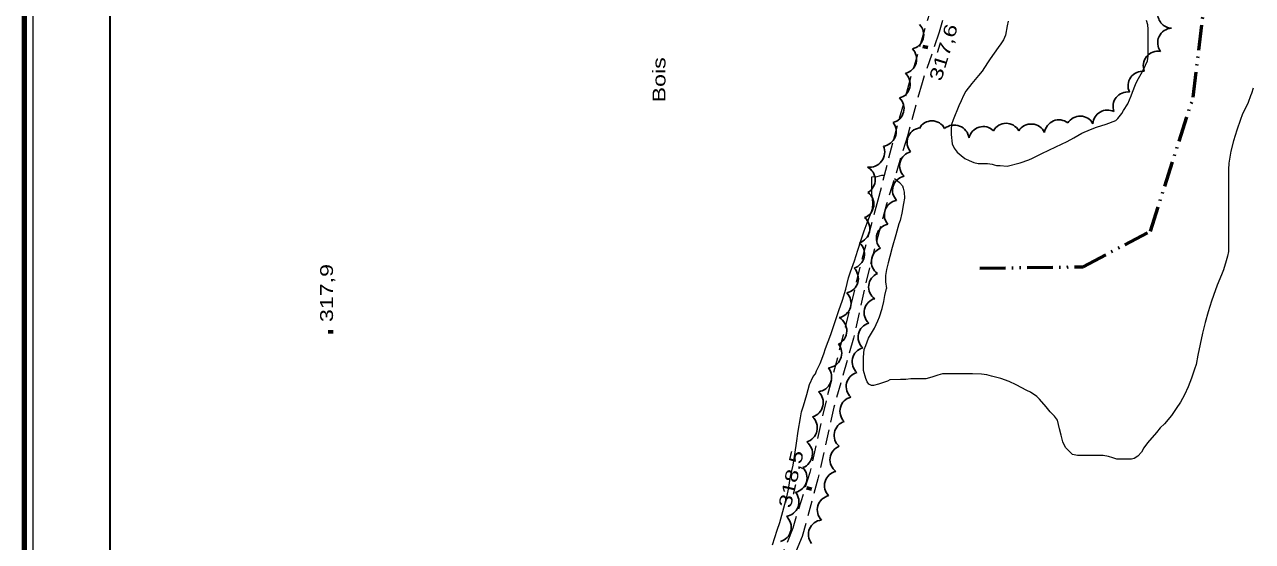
# Model space of a CAD drawing. Extents: x 240591 to 242335, y 5323482 to 5326937.
# Drawn here: x 240590.8 to 240877.4, y 5323830.7 to 5323951.4 of the extents above; entities that cross this region are included whole.
import ezdxf
from ezdxf.enums import TextEntityAlignment as Align

# ---------------------------------------------------------------- set-up
doc = ezdxf.new("R2010")
doc.units = 0
doc.header["$LTSCALE"] = 1.2
for name, pattern in [('DASH_DOUBLE_DOT', [9.2, 5, -1.2, 0.3, -1.2, 0.3, -1.2]), ('LONG_DASHED', [7.5, 6, -1.5]), ('MEDIUM_DASHED', [4.5, 3, -1.5])]:
    doc.linetypes.add(name, pattern=pattern)
for name, color, linetype, lineweight in [('19', 7, 'Continuous', 13), ('2', 7, 'Continuous', 13), ('3', 7, 'Continuous', 140), ('4', 7, 'DASH_DOUBLE_DOT', 53), ('44', 7, 'Continuous', 25), ('60', 7, 'Continuous', 35)]:
    doc.layers.add(name, color=color, linetype=linetype, lineweight=lineweight)

msp = doc.modelspace()

# ---------------------------------------------------------------- linework, layer by layer
at = {"layer": '19', "linetype": 'MEDIUM_DASHED'}
for points in [[(240808, 5323962.7), (240804.3, 5323949.6), (240800.3, 5323937.8), (240796.9, 5323925.3), (240792, 5323909.4), (240788, 5323894.6), (240784.3, 5323878.1), (240779.7, 5323862), (240776, 5323845.3), (240772.3, 5323831.8), (240767.8, 5323821.1)], [(240804.2, 5323960.8), (240800.7, 5323949.6), (240797.4, 5323938.1), (240793.4, 5323923.7), (240790, 5323910.4), (240785.8, 5323894.7), (240781.9, 5323878.8), (240777.9, 5323863.5), (240774.1, 5323846.8), (240770.1, 5323833.8), (240765.6, 5323822.3)]]:
    msp.add_lwpolyline(points, dxfattribs=at)
at = {"layer": '2'}
for points in [[(240820.4, 5323952.2), (240820.2, 5323951.1), (240819.8, 5323948.9), (240819.3, 5323947.8), (240818.7, 5323946.9), (240818.1, 5323946), (240816.2, 5323943.4), (240815.6, 5323942.4), (240814.3, 5323940.5), (240813.5, 5323939.5), (240811.9, 5323937.6), (240810.5, 5323935.8), (240810, 5323934.8), (240809.4, 5323933.6), (240808.9, 5323932.4), (240807.6, 5323929.1), (240807.2, 5323928), (240807.1, 5323926.9), (240807.1, 5323925.7), (240807.3, 5323923.5), (240807.8, 5323922.5), (240808.5, 5323921.6), (240809.4, 5323920.8), (240810.3, 5323920.1), (240811.3, 5323919.6), (240812.4, 5323919.2), (240813.4, 5323918.9), (240814.3, 5323918.9), (240815.6, 5323918.9), (240816.7, 5323918.8), (240817.1, 5323918.6), (240817.7, 5323918.5), (240818.5, 5323918.5), (240820.2, 5323918.3)], [(240820.2, 5323918.3), (240823.2, 5323919.1), (240825.2, 5323919.8), (240826.1, 5323920.2), (240828.3, 5323921.3), (240831.5, 5323922.8), (240834.2, 5323924.1), (240835.7, 5323924.9), (240837.6, 5323926), (240839.6, 5323926.9), (240841, 5323927.4), (240843.3, 5323928.1), (240845.5, 5323929), (240846, 5323929.4), (240846.9, 5323930.6), (240847.3, 5323931.3), (240848.3, 5323932.9), (240849.1, 5323934.7), (240849.4, 5323935.6), (240850.1, 5323937.4), (240850.5, 5323938.2), (240851.8, 5323940.4), (240852.5, 5323941.9), (240852.9, 5323942.9), (240853.1, 5323944), (240853.1, 5323945), (240853.1, 5323947.1), (240853.1, 5323950.3), (240853, 5323951.3), (240852.7, 5323952.3)], [(240788.6, 5323915.8), (240789.8, 5323915.9), (240790.9, 5323916.2), (240791.5, 5323916.2)], [(240793.9, 5323915.4), (240794.2, 5323915.2), (240795, 5323914.5), (240795.7, 5323913.7), (240795.9, 5323913.2), (240796.1, 5323912.2), (240796.2, 5323910.8), (240796, 5323909.6), (240795.6, 5323907.3), (240795.2, 5323905.6), (240794.9, 5323904.8), (240794.2, 5323902.3), (240793.3, 5323899.3), (240792.8, 5323897.2), (240792.4, 5323895.7), (240792, 5323894.2), (240791.8, 5323892.8), (240791.8, 5323891.3), (240792, 5323889.7)]]:
    msp.add_lwpolyline(points, dxfattribs=at)
at = {"layer": '2', "linetype": 'LONG_DASHED'}
for points in [[(240877.6, 5323936.5), (240877.2, 5323935.3), (240877, 5323934.7), (240876.4, 5323933.2), (240875, 5323930.3), (240874.6, 5323929.2), (240873.8, 5323926.7), (240873, 5323924.2), (240872.4, 5323921.8), (240871.9, 5323919), (240871.8, 5323917.5), (240871.8, 5323916), (240871.8, 5323913.2), (240871.8, 5323910.5), (240871.8, 5323907.9), (240871.8, 5323905.3), (240871.8, 5323901.8), (240871.8, 5323898.4), (240871.6, 5323897.3), (240871.3, 5323896.2), (240870.7, 5323894.1), (240870.2, 5323892.9), (240869.2, 5323890.5), (240868.3, 5323888.1), (240867.9, 5323886.8), (240867.1, 5323884.3), (240866.4, 5323881.8), (240865.8, 5323879.3), (240865.2, 5323876.7), (240864.7, 5323874.2), (240864.3, 5323872), (240863.9, 5323870.9), (240863.2, 5323868.8), (240862.4, 5323866.8), (240861.6, 5323864.9), (240860.6, 5323863.2), (240859.6, 5323861.7), (240858.5, 5323860.1), (240856.9, 5323858.1), (240855.9, 5323857.2), (240855, 5323856.1), (240852.9, 5323853.7), (240852.1, 5323852.5), (240851.5, 5323851.5), (240850.7, 5323850.6), (240849.8, 5323850), (240849.2, 5323849.9), (240848.6, 5323849.9), (240845.8, 5323849.9), (240844.8, 5323850.2), (240843.8, 5323850.5), (240842.6, 5323850.7)], [(240765.4, 5323829.9), (240766.5, 5323833.3), (240767.1, 5323835.1), (240768, 5323838.5), (240768.8, 5323841.4), (240769.1, 5323842.9), (240769.6, 5323845.8), (240770.2, 5323848.5), (240770.7, 5323851.5), (240771, 5323853.6), (240771.4, 5323856.4), (240771.9, 5323859.5), (240772.2, 5323860.9), (240772.6, 5323862.3), (240773.4, 5323865), (240774, 5323867.3), (240774.9, 5323869.2), (240775.4, 5323869.8), (240775.7, 5323870.5), (240776.5, 5323872.2), (240777.4, 5323874.5), (240777.8, 5323875.7), (240779, 5323879), (240780.1, 5323882.3), (240780.9, 5323884.6), (240781.7, 5323887), (240782.5, 5323889.6), (240783.1, 5323892.2), (240783.6, 5323893.6), (240784.5, 5323896.2), (240785.3, 5323898.7), (240786.1, 5323901.1), (240786.8, 5323903.2), (240787.5, 5323905.1), (240788.2, 5323906.9), (240788.7, 5323908.4), (240788.8, 5323909.6), (240788.7, 5323910.7), (240788.6, 5323911.9), (240788.6, 5323913.4), (240788.6, 5323915.8)], [(240842.6, 5323850.7), (240841.9, 5323850.7), (240839.2, 5323850.7), (240836.6, 5323850.7), (240835.4, 5323851), (240834.8, 5323851.6), (240833.9, 5323852.5), (240833.5, 5323853.2), (240833.2, 5323853.9), (240832.8, 5323855.5), (240832.4, 5323857), (240831.9, 5323859), (240831.2, 5323859.9), (240830.2, 5323860.9), (240829.3, 5323862.1), (240827.7, 5323863.9), (240827.1, 5323864.5), (240825.6, 5323865.5), (240824.8, 5323865.9), (240822.3, 5323867.2), (240820.6, 5323868), (240818.7, 5323868.7), (240816.5, 5323869.3), (240815.4, 5323869.6), (240814.2, 5323869.7), (240812.1, 5323869.8), (240810.3, 5323869.8), (240807.7, 5323869.8), (240805.1, 5323869.8), (240804, 5323869.5), (240802.6, 5323869), (240801.2, 5323868.6), (240800.6, 5323868.6), (240797.7, 5323868.6), (240796.5, 5323868.5), (240795.3, 5323868.5), (240792.8, 5323868.4), (240792.2, 5323868.1), (240790.1, 5323867.4), (240789, 5323867.1), (240788.5, 5323867.1), (240787.9, 5323867.4), (240787.5, 5323867.9), (240787.2, 5323868.7), (240786.6, 5323870.6), (240786.6, 5323871.6), (240786.6, 5323873.7), (240786.8, 5323875.5), (240787.2, 5323876.4), (240787.8, 5323878.1), (240788.7, 5323879.7), (240789.2, 5323880.5), (240790, 5323882.2), (240790.4, 5323883.1), (240791, 5323885.1), (240791.4, 5323886.7), (240791.6, 5323888.1), (240792, 5323889.7)]]:
    msp.add_lwpolyline(points, dxfattribs=at)
at = {"layer": '3'}
for p, q in [((240801, 5323945.8), (240801.2, 5323946.6)), ((240662.3, 5323879.2), (240662.3, 5323880)), ((240773.9, 5323842.6), (240774.1, 5323843.4))]:
    msp.add_line(p, q, dxfattribs=at)
at = {"layer": '4'}
msp.add_lwpolyline([(240813.8, 5323894.5), (240837.9, 5323894.8), (240853.6, 5323903.1), (240863.6, 5323934.4), (240867.4, 5323966.2), (240874.6, 5323997.3), (240880.9, 5324027.7), (240887.7, 5324063.3), (240891.8, 5324094.2), (240896.6, 5324123.1), (240898.9, 5324148.6), (240898.9, 5324169.8), (240897.6, 5324189.2), (240897.7, 5324201.4)], dxfattribs=at)
at = {"layer": '44'}
for centre, radius, start, end in [((240802.62, 5323925.541), 3.351, 27.92996, 151.68225), ((240807.813, 5323924.429), 3.489, 7.75394, 129.79364), ((240800.15, 5323923.9), 3.358, 98.34055, 221.61662), ((240798.46, 5323918.382), 3.389, 104.011, 225.61465), ((240791.212, 5323890.133), 3.38, 113.21534, 235.13197), ((240775.741, 5323869.075), 3.457, 276.45615, 38.14352), ((240773.797, 5323863.102), 3.448, 285.53051, 47.41147), ((240772.404, 5323857.217), 3.455, 286.24113, 47.89776), ((240771.27, 5323851.154), 3.457, 290.65989, 52.59729), ((240770.016, 5323845.518), 3.449, 282.46556, 44.15418), ((240768.142, 5323839.921), 3.439, 278.50349, 40.40673), ((240766.317, 5323833.982), 3.448, 285.53051, 47.41147)]:
    msp.add_arc(centre, radius, start, end, dxfattribs=at)
for centre, major_axis, ratio, start_param, end_param in [((240858.723, 5323953.882), (-2.989, -1.624), 0.982656, 5.6144268, 7.3004285), ((240797.306, 5323949.008), (3.255, -0.955), 0.999635, 5.2187518, 7.3432747), ((240858.7, 5323947.142), (-2.654, 2.122), 0.997268, 5.4414369, 7.597625), ((240795.648, 5323943.304), (2.949, -1.678), 0.999926, 5.4593403, 7.5848665), ((240855.383, 5323941.73), (-2.591, 2.277), 0.997201, 5.2577619, 7.3799209), ((240794.133, 5323937.494), (3.308, -0.769), 0.998722, 5.2168221, 7.3432066), ((240851.809, 5323937.066), (-2.805, 1.974), 0.997536, 5.2159353, 7.3369463), ((240792.7, 5323931.788), (3.292, -0.85), 0.998545, 5.2172951, 7.3390435), ((240848.28, 5323932.233), (-1.983, -2.767), 0.999937, 3.6368045, 5.6841444), ((240843.586, 5323928.003), (0.119, -3.407), 0.999846, 2.6520936, 4.6148704), ((240790.888, 5323926.386), (-0.474, 3.366), 0.999994, 3.1173898, 5.2435517), ((240819.92, 5323924.934), (-0.019, 3.386), 0.996974, 5.2142814, 7.3406298), ((240825.773, 5323924.697), (0.224, 3.454), 0.999951, 5.2202413, 7.3434146), ((240832.24, 5323925.759), (-1.29, 3.117), 0.997204, 5.2161728, 7.3373189), ((240837.214, 5323926.648), (0.314, 3.346), 0.999977, 5.2910443, 7.402616), ((240814.586, 5323924.16), (-0.951, 3.261), 0.999994, 5.2214567, 7.3505676), ((240788.059, 5323921.592), (2.801, -2.132), 0.999573, 5.217798, 7.3485993), ((240785.96, 5323915.104), (3.322, -0.728), 0.999927, 5.4583188, 7.5830805), ((240796.809, 5323912.65), (-3.238, 0.995), 0.999977, 5.2244729, 7.3480109), ((240785.65, 5323909.455), (3.36, -0.458), 0.999635, 5.2222284, 7.3473801), ((240794.883, 5323906.952), (-3.172, 1.191), 0.999794, 5.2233113, 7.3461078), ((240784.635, 5323903.688), (3.386, -0.683), 0.998591, 5.2184735, 7.3414616), ((240793.009, 5323901.457), (0.78, -3.287), 0.999994, 3.1200463, 5.2436113), ((240783.427, 5323897.793), (3.187, -1.312), 0.999885, 5.4013017, 7.5315982), ((240791.868, 5323895.987), (2.735, -2.005), 0.999983, 2.5961844, 4.7183201), ((240781.982, 5323892.083), (3.195, -1.297), 0.999598, 5.3197103, 7.445918), ((240780.255, 5323886.312), (3.246, -1.208), 0.999001, 5.2821636, 7.409346), ((240790.172, 5323884.089), (-3.131, 1.303), 0.999824, 5.3729515, 7.4977709), ((240779.186, 5323879.88), (3.517, -0.44), 0.99962, 5.3189257, 7.4445552), ((240788.76, 5323878.345), (-3.289, 0.808), 0.999794, 5.2220715, 7.3482309), ((240778.097, 5323874.638), (3.188, -1.336), 0.996564, 5.2130848, 7.3370458), ((240787.372, 5323872.601), (-3.292, 0.789), 0.999794, 5.2202599, 7.3454395), ((240785.989, 5323866.852), (-3.288, 0.8), 0.999427, 5.2227786, 7.3457876), ((240784.506, 5323861.091), (-3.267, 0.875), 0.998535, 5.2175315, 7.3445218), ((240783.164, 5323855.44), (-3.314, 0.692), 0.999949, 5.2225239, 7.3468556), ((240782.194, 5323849.735), (1.329, -3.111), 0.999994, 3.1145839, 5.2451872), ((240780.915, 5323843.703), (-2.925, 1.705), 0.999926, 5.4556615, 7.5875216), ((240779.226, 5323838.031), (-3.236, 0.972), 0.999948, 5.2207893, 7.3487265), ((240777.184, 5323832.302), (-3.125, 1.318), 0.999178, 5.2219829, 7.3441446)]:
    msp.add_ellipse(centre, major_axis=major_axis, ratio=ratio, start_param=start_param, end_param=end_param, dxfattribs=at)
at = {"layer": '60', "lineweight": 158}
msp.add_lwpolyline([(242321.7, 5323482.5), (240590.8, 5323482.5), (240590.8, 5326907.9), (242321.7, 5326907.9)], close=True, dxfattribs=at)
at = {"layer": '60', "lineweight": 13}
msp.add_lwpolyline([(240592.8, 5323484.5), (240592.8, 5326905.9), (242319.7, 5326905.9), (242319.7, 5323484.5)], close=True, dxfattribs=at)
at = {"layer": '60'}
msp.add_lwpolyline([(240610.8, 5326369.9), (242301.7, 5326369.9), (242301.7, 5323502.5), (240610.8, 5323502.5)], close=True, dxfattribs=at)

# ---------------------------------------------------------------- texts
at = {"layer": '3', "width": 1.35}
for s, rotation, p in [('317,6', 73.016, (240806.735, 5323944.462)), ('318,5', 76.916, (240771.183, 5323844.91))]:
    msp.add_text(s, height=3, rotation=rotation, dxfattribs=at).set_placement(p, align=Align.CENTER)
msp.add_text('317,9', height=3, rotation=90, dxfattribs=at).set_placement((240662.8, 5323881.9))
at = {"layer": '44', "width": 1.35}
msp.add_text('Bois', height=3, rotation=90, dxfattribs=at).set_placement((240740.4, 5323933.2))

doc.saveas('drawing.dxf')
